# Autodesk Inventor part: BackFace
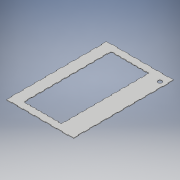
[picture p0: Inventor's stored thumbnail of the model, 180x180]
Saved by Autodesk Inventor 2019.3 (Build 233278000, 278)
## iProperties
Created: 2020-02
Part Number: BackFace
Material: Generic
Document SubType Name: Modeling
Designer: KrystynWikoff
Density: 1 g/cm^3
Appearance: Default
Author: KrystynWikoff
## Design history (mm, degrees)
sketch "Sketch1"
  geometry: L1 (0, 0)-(304.8, 0); L2 (304.8, 0)-(304.8, -457.2); L3 (304.8, -457.2)-(0, -457.2); L4 (0, -457.2)-(0, 0); L5 (254, -31.75)-(84.582, -31.75); L6 (84.582, -31.75)-(84.582, -425.45); L7 (84.582, -425.45)-(254, -425.45); L8 (254, -425.45)-(254, -31.75)
  constraints: 16 end point, 4 parallel, 2 horizontal, 2 perpendicular
  dimensions: "d0" = 457.2 distance of L1.end L2.end; "d1" = 304.8 distance of L1.start L1.end; "d2" = 31.75 distance between parallel lines of L1 L5; "d3" = 31.75 distance between parallel lines of L3 L7; "d4" = 50.8 distance between parallel lines of L2 L8; "d5" = 84.582 distance between parallel lines of L4 L6
extrude "Extrusion1" new body sketch "Sketch1" distance "d6" = 2.3622; taper "d7" = 0 deg
sketch "Sketch2" dims "d16" = 25.4, "d26" = 25.4, "d35" = 25.4, "d44" = 25.4
  geometry: L1 (0, 0)-(0, 457.2) reference; L2 (0, 25.4)-(-2.362, 25.4); L3 (-2.362, 25.4)-(-2.362, 50.8); L4 (-2.362, 50.8)-(0, 50.8); L5 (0, 50.8)-(0, 25.4); L6 (-304.8, 0)-(0, 0) reference; L7 (0, 76.2)-(-2.362, 76.2); L8 (-2.362, 76.2)-(-2.362, 101.6); L9 (-2.362, 101.6)-(0, 101.6); L10 (0, 101.6)-(0, 76.2); L11 (0, 127)-(-2.362, 127); L12 (-2.362, 127)-(-2.362, 152.4); L13 (-2.362, 152.4)-(0, 152.4); L14 (0, 152.4)-(0, 127); L15 (0, 177.8)-(-2.362, 177.8); L16 (-2.362, 177.8)-(-2.362, 203.2); L17 (-2.362, 203.2)-(0, 203.2); L18 (0, 203.2)-(0, 177.8); L19 (0, 228.6)-(-2.362, 228.6); L20 (-2.362, 228.6)-(-2.362, 254); L21 (-2.362, 254)-(0, 254); L22 (0, 254)-(0, 228.6); L23 (0, 279.4)-(-2.362, 279.4); L24 (-2.362, 279.4)-(-2.362, 304.8); L25 (-2.362, 304.8)-(0, 304.8); L26 (0, 304.8)-(0, 279.4); L27 (0, 330.2)-(-2.362, 330.2); L28 (-2.362, 330.2)-(-2.362, 355.6); L29 (-2.362, 355.6)-(0, 355.6); L30 (0, 355.6)-(0, 330.2); L31 (0, 381)-(-2.362, 381); L32 (-2.362, 381)-(-2.362, 406.4); L33 (-2.362, 406.4)-(0, 406.4); L34 (0, 406.4)-(0, 381); L35 (0, 431.8)-(-2.362, 431.8); L36 (-2.362, 431.8)-(-2.362, 457.2); L37 (-2.362, 457.2)-(0, 457.2); L38 (0, 457.2)-(0, 431.8); L39 (0, 0)-(-25.4, 0); L40 (-25.4, 0)-(-25.4, 2.362); L41 (-25.4, 2.362)-(0, 2.362); L42 (0, 2.362)-(0, 0); L43 (-76.2, 2.362)-(-50.8, 2.362); L44 (-50.8, 2.362)-(-50.8, 0); L45 (-76.2, 0)-(-76.2, 2.362); L46 (-50.8, 0)-(-76.2, 0); L47 (-127, 2.362)-(-101.6, 2.362); L48 (-101.6, 2.362)-(-101.6, 0); L49 (-127, 0)-(-127, 2.362); L50 (-101.6, 0)-(-127, 0); L51 (-177.8, 2.362)-(-152.4, 2.362); L52 (-152.4, 2.362)-(-152.4, 0); L53 (-177.8, 0)-(-177.8, 2.362); L54 (-152.4, 0)-(-177.8, 0); L55 (-228.6, 2.362)-(-203.2, 2.362); L56 (-203.2, 2.362)-(-203.2, 0); L57 (-228.6, 0)-(-228.6, 2.362); L58 (-203.2, 0)-(-228.6, 0); L59 (-279.4, 2.362)-(-254, 2.362); L60 (-254, 2.362)-(-254, 0); L61 (-279.4, 0)-(-279.4, 2.362); L62 (-254, 0)-(-279.4, 0); L63 (-304.8, 0)-(-302.438, 0); L64 (-302.438, 0)-(-302.438, 25.4)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
  constraints: 240 end point, 8 parallel, 6 horizontal, 4 perpendicular, 2 point on line, 2 vertical, 1 collinear, 207 other
  dimensions: "d8" = 25.4 distance between parallel lines of L6 L2; "d9" = 25.4 distance of L2.end L3.end; "d10" = 2.3622 distance of L3.end L4.end; "d13" = 50.8 distance of L2.start L7.start; "d18" = 0 distance between parallel lines of L1 L42; "d19" = 25.4 distance of L40.end L41.end; "d20" = 2.3622 distance of L39.end L40.end; "d23" = 50.8 distance of L41.end L43.end; "d28" = 2.3622 distance of L64.end L65.end; "d29" = 25.4 distance of L63.end L64.end; "d32" = 50.8 distance of L63.end L67.start; "d37" = 25.4 distance of L101.end L102.end; "d38" = 2.3622 distance of L100.end L101.end; "d41" = 50.8 distance of L101.end L104.end
extrude "Extrusion2" cut sketch "Sketch2" distance "d46" = 2.9972; taper "d47" = 0 deg
sketch "Sketch4" dims "d71" = 25.4, "d81" = 25.4, "d91" = 25.4, "d100" = 25.4
  geometry: L1 (-84.582, 47.625)-(-82.22, 47.625); L2 (-82.22, 47.625)-(-82.22, 66.675); L3 (-82.22, 66.675)-(-84.582, 66.675); L4 (-84.582, 66.675)-(-84.582, 47.625); L5 (-84.582, 425.45)-(-84.582, 31.75) reference; L6 (-84.582, 31.75)-(-254, 31.75) reference; L7 (-84.582, 85.725)-(-82.22, 85.725); L8 (-82.22, 85.725)-(-82.22, 104.775); L9 (-82.22, 104.775)-(-84.582, 104.775); L10 (-84.582, 104.775)-(-84.582, 85.725); L11 (-84.582, 123.825)-(-82.22, 123.825); L12 (-82.22, 123.825)-(-82.22, 142.875); L13 (-82.22, 142.875)-(-84.582, 142.875); L14 (-84.582, 142.875)-(-84.582, 123.825); L15 (-84.582, 161.925)-(-82.22, 161.925); L16 (-82.22, 161.925)-(-82.22, 180.975); L17 (-82.22, 180.975)-(-84.582, 180.975); L18 (-84.582, 180.975)-(-84.582, 161.925); L19 (-84.582, 200.025)-(-82.22, 200.025); L20 (-82.22, 200.025)-(-82.22, 219.075); L21 (-82.22, 219.075)-(-84.582, 219.075); L22 (-84.582, 219.075)-(-84.582, 200.025); L23 (-84.582, 238.125)-(-82.22, 238.125); L24 (-82.22, 238.125)-(-82.22, 257.175); L25 (-82.22, 257.175)-(-84.582, 257.175); L26 (-84.582, 257.175)-(-84.582, 238.125); L27 (-84.582, 276.225)-(-82.22, 276.225); L28 (-82.22, 276.225)-(-82.22, 295.275); L29 (-82.22, 295.275)-(-84.582, 295.275); L30 (-84.582, 295.275)-(-84.582, 276.225); L31 (-84.582, 314.325)-(-82.22, 314.325); L32 (-82.22, 314.325)-(-82.22, 333.375); L33 (-82.22, 333.375)-(-84.582, 333.375); L34 (-84.582, 333.375)-(-84.582, 314.325); L35 (-84.582, 352.425)-(-82.22, 352.425); L36 (-82.22, 352.425)-(-82.22, 371.475); L37 (-82.22, 371.475)-(-84.582, 371.475); L38 (-84.582, 371.475)-(-84.582, 352.425); L39 (-84.582, 390.525)-(-82.22, 390.525); L40 (-82.22, 390.525)-(-82.22, 409.575); L41 (-82.22, 409.575)-(-84.582, 409.575); L42 (-84.582, 409.575)-(-84.582, 390.525); L43 (-254, 31.75)-(-254, 425.45) reference; L44 (-254, 47.625)-(-256.362, 47.625); L45 (-256.362, 47.625)-(-256.362, 66.675); L46 (-256.362, 66.675)-(-254, 66.675); L47 (-254, 66.675)-(-254, 47.625); L48 (-256.362, 104.775)-(-254, 104.775); L49 (-254, 104.775)-(-254, 85.725); L50 (-254, 85.725)-(-256.362, 85.725); L51 (-256.362, 85.725)-(-256.362, 104.775); L52 (-256.362, 142.875)-(-254, 142.875); L53 (-254, 142.875)-(-254, 123.825); L54 (-254, 123.825)-(-256.362, 123.825); L55 (-256.362, 123.825)-(-256.362, 142.875); L56 (-256.362, 180.975)-(-254, 180.975); L57 (-254, 180.975)-(-254, 161.925); L58 (-254, 161.925)-(-256.362, 161.925); L59 (-256.362, 161.925)-(-256.362, 180.975); L60 (-256.362, 219.075)-(-254, 219.075); L61 (-254, 219.075)-(-254, 200.025); L62 (-254, 200.025)-(-256.362, 200.025); L63 (-256.362, 200.025)-(-256.362, 219.075); L64 (-256.362, 257.175)-(-254, 257.175)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; 1 further point
  constraints: 272 end point, 8 parallel, 6 horizontal, 4 perpendicular, 2 point on line, 2 vertical, 1 collinear, 239 other
  dimensions: "d62" = 19.05 distance of L1.end L2.end; "d63" = 0 distance between parallel lines of L5 L4; "d64" = 15.875 distance between parallel lines of L6 L1; "d65" = 2.3622 distance of L1.start L1.end; "d68" = 38.1 distance of L1.start L7.start; "d73" = 15.875 distance from line of L6.end L44; "d74" = 19.05 distance of L44.end L45.end; "d75" = 2.3622 distance of L44.start L44.end; "d78" = 38.1 distance of L45.end L48.start; "d83" = 2.3622 distance of L84.end L85.end; "d84" = 12.7 distance of L85.end L86.end; "d85" = 0 distance between parallel lines of L5 L87; "d88" = 25.4 distance of L84.end L88.end; "d93" = 12.7 distance of L113.end L114.end; "d94" = 2.3622 distance of L112.end L113.end; "d97" = 25.4 distance of L112.end L116.end
extrude "Extrusion4" cut sketch "Sketch4" distance "d102" = 2.9972; taper "d103" = 0 deg
sketch "Sketch5"
  geometry: L1 (-50.8, 0)-(-25.4, 0) reference; L2 (0, 203.2)-(0, 228.6) reference; L3 (-2.362, 457.2)-(-25.4, 457.2) reference; C1 r 9.525 at (-25.4, 419.1); 1 further point
  constraints: 1 centre point
  dimensions: "d104" = 19.05 diameter of C1; "d106" = 25.4 distance from line of L2 C1.centre; "d109" = 38.1 distance from line of L3 C1.centre
extrude "Extrusion5" cut sketch "Sketch5" distance "d107" = 25.4; taper "d108" = 0 deg
body "Solid1"
